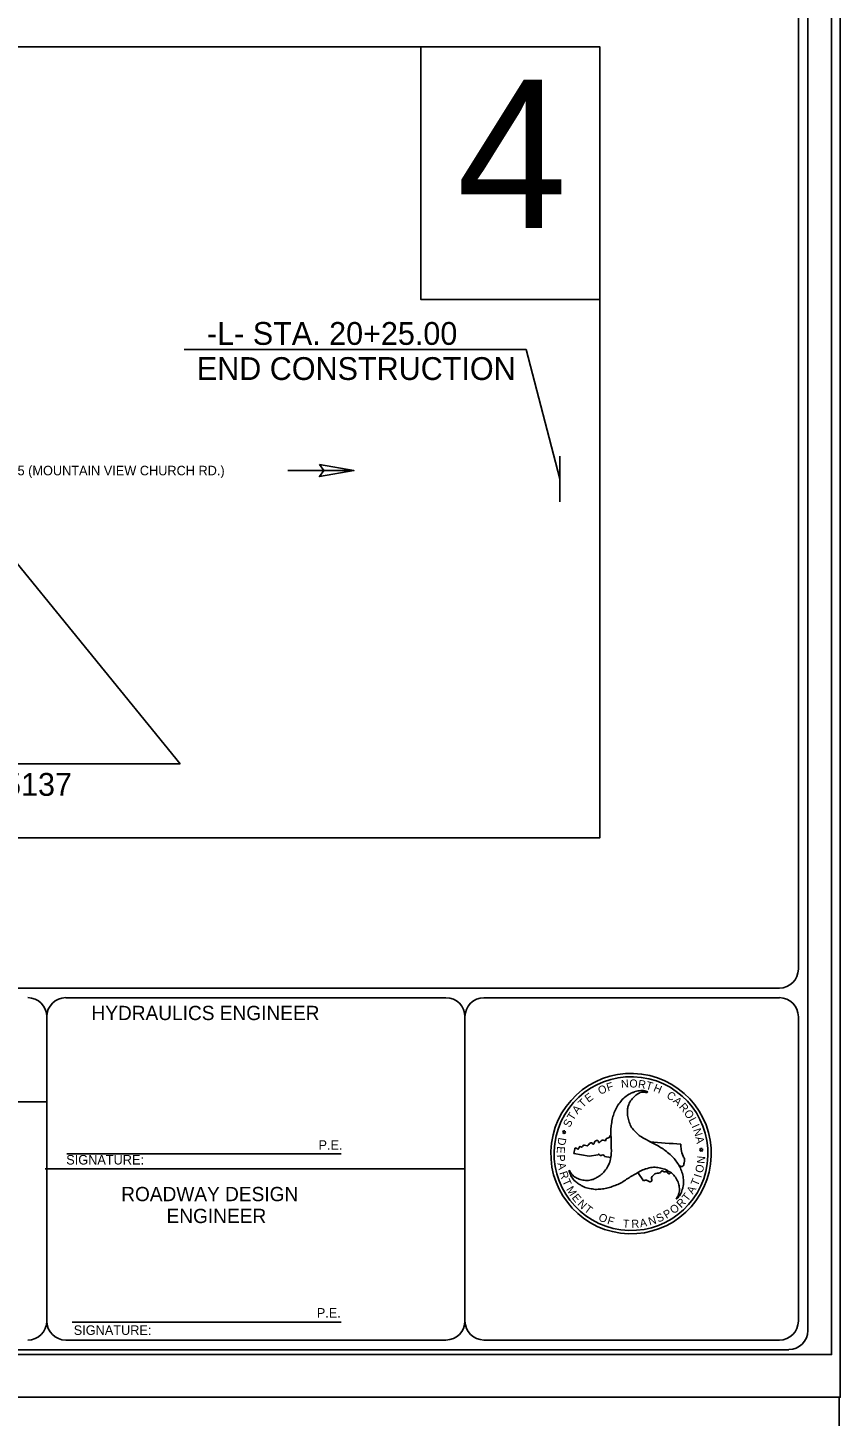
# Model space of a CAD drawing. Extents: x 1664524 to 1666208, y 587901 to 592296.
# Drawn here: x 1665781 to 1666208, y 591186 to 591916 of the extents above; entities that cross this region are included whole.
import ezdxf

# ---------------------------------------------------------------- set-up
doc = ezdxf.new("R2010")
doc.units = 0
for name, color, linetype in [('Default', 7, 'Continuous'), ('Prop Horizontal Alignment Station Label', 7, 'Continuous'), ('Prop Horizontal Alignment Tick Large', 7, 'Continuous'), ('Prop Horizontal Alignment Tick Small', 7, 'Continuous'), ('Prop Terminator CELL', 7, 'Continuous'), ('Sheet Cutting Line CELL', 7, 'Continuous')]:
    doc.layers.add(name, color=color, linetype=linetype)

msp = doc.modelspace()

# ---------------------------------------------------------------- linework, layer by layer
at = {"layer": 'Default'}
for p, q in [((1665863.04, 591747.15), (1666042.63, 591747.15)), ((1666042.63, 591747.15), (1666060.35, 591679.09)), ((1666060.39, 591667.09), (1666060.32, 591691.1)), ((1665860.89, 591529.38), (1665735.9, 591682.77)), ((1665917.52, 591683.48), (1665952.16, 591683.48)), ((1665860.89, 591529.38), (1665603.77, 591529.35))]:
    msp.add_line(p, q, dxfattribs=at)
for points in [[(1665085.75, 591906.14), (1666081.5, 591906.14), (1666081.5, 591490.46), (1665085.75, 591490.46)], [(1666081.5, 591906.14), (1665987.3, 591906.14), (1665987.3, 591773.47), (1666081.5, 591773.47)]]:
    msp.add_lwpolyline(points, close=True, dxfattribs=at)
at = {"layer": 'Prop Horizontal Alignment Station Label'}
for p, q in [((1664755.76, 591411.35), (1666175.76, 591411.35)), ((1665800.76, 591406.35), (1666000.53, 591406.35)), ((1666020.53, 591406.35), (1666175.76, 591406.35)), ((1665790.76, 591236.34), (1665790.76, 591396.34)), ((1666010.53, 591236.35), (1666010.53, 591396.35)), ((1666106.66, 591356.95), (1666106.58, 591356.87)), ((1666106.66, 591356.95), (1666106.58, 591356.87)), ((1665790.76, 591351.59), (1665485.76, 591351.6)), ((1666062.24, 591335.67), (1666061.72, 591336.19)), ((1666061.72, 591336.19), (1666062.45, 591336.09)), ((1666061.94, 591335.01), (1666062.24, 591335.67)), ((1666062.55, 591335.37), (1666061.94, 591335.01)), ((1666062.45, 591336.09), (1666062.74, 591336.73)), ((1666063.09, 591334.86), (1666062.55, 591335.37)), ((1666062.74, 591336.73), (1666062.89, 591336.03)), ((1666062.89, 591336.03), (1666063.61, 591335.93)), ((1666063.61, 591335.93), (1666062.96, 591335.58)), ((1666062.96, 591335.58), (1666063.09, 591334.86)), ((1666107.72, 591330.68), (1666107.72, 591330.68)), ((1666134.81, 591327.38), (1666134.5, 591326.74)), ((1666134.97, 591326.68), (1666134.81, 591327.38)), ((1665801.25, 591324.36), (1665945.5, 591324.36)), ((1666067.84, 591324.41), (1666068.26, 591326.92)), ((1666075.73, 591323.06), (1666067.84, 591324.41)), ((1666080.46, 591323.79), (1666075.73, 591323.06)), ((1666087.19, 591322.33), (1666083.88, 591322.81)), ((1666134.5, 591326.74), (1666133.78, 591326.84)), ((1666133.78, 591326.84), (1666134.32, 591326.34)), ((1666134.32, 591326.34), (1666134.01, 591325.67)), ((1666134.01, 591325.67), (1666134.63, 591326.02)), ((1666134.63, 591326.02), (1666135.15, 591325.52)), ((1666135.68, 591326.61), (1666134.97, 591326.68)), ((1666135.03, 591326.24), (1666135.68, 591326.61)), ((1666135.15, 591325.52), (1666135.03, 591326.24)), ((1665789.86, 591316.37), (1666010.53, 591316.37)), ((1666104.38, 591310.17), (1666101.38, 591314.44)), ((1666101.38, 591314.44), (1666101.38, 591314.44)), ((1666139.63, 591318.87), (1666139.63, 591318.87)), ((1665804.01, 591235.8), (1665945.51, 591235.79))]:
    msp.add_line(p, q, dxfattribs=at)
for points in [[(1666185.76, 591421.34), (1666185.76, 592256.35)], [(1666190.76, 591231.35), (1666190.76, 592261.34)], [(1666185.76, 591236.35), (1666185.76, 591396.35)], [(1665800.76, 591226.35), (1666000.53, 591226.35)], [(1666020.53, 591226.35), (1666175.76, 591226.35)], [(1664700.76, 591221.34), (1666180.76, 591221.34)]]:
    msp.add_lwpolyline(points, dxfattribs=at)
for centre, radius, start, end in [((1666175.76, 591421.39), 10, 270, 360), ((1665780.76, 591396.39), 10, 0, 90), ((1665800.76, 591396.39), 10, 90, 180), ((1666000.53, 591396.35), 10, 0, 90), ((1666020.53, 591396.35), 10, 90, 180), ((1666175.76, 591396.39), 10, 0, 90), ((1666097.83, 591324.42), 42.17, 352.42113, 172.42113), ((1666097.83, 591324.42), 40.42, 352.42113, 172.42113), ((1666097.83, 591324.42), 42.17, 172.42113, 352.42113), ((1666097.83, 591324.42), 40.42, 172.42113, 352.42113), ((1666132.74, 591551.63), 222.36, 258.09962, 258.19922), ((1666132.74, 591551.63), 222.36, 263.53868, 267.74469), ((1665780.76, 591236.39), 10, 270, 360), ((1665800.76, 591236.39), 10, 180, 270), ((1666000.53, 591236.41), 10, 270, 360), ((1666020.53, 591236.41), 10, 180, 270), ((1666175.76, 591236.39), 10, 270, 360), ((1666180.76, 591231.39), 10, 270, 360)]:
    msp.add_arc(centre, radius, start, end, dxfattribs=at)
for points in [[(1666106.58, 591356.87), (1666105.67, 591357.25), (1666102.88, 591357.51), (1666099.93, 591356.98), (1666099.66, 591356.87), (1666098.15, 591356.32), (1666096.51, 591355.4), (1666093.95, 591353.56), (1666091.87, 591351.15), (1666091.02, 591350.12), (1666090.33, 591348.8), (1666089.01, 591345.97), (1666088.15, 591343.19), (1666087.52, 591339.88), (1666087.18, 591336.95), (1666087.26, 591333.9), (1666087.38, 591330.82), (1666087.43, 591327.83), (1666087.44, 591324.77), (1666087.05, 591321.78), (1666087, 591321.52), (1666086.05, 591318.41), (1666084.39, 591315.79), (1666082.42, 591313.67), (1666081.29, 591312.72), (1666079.75, 591311.82), (1666078.87, 591311.29), (1666076.85, 591310.58), (1666073.9, 591310.29), (1666071.12, 591310.82), (1666068.72, 591311.79), (1666066.73, 591313.48), (1666065.27, 591315.71)], [(1666121.6, 591300.54), (1666122.33, 591301.12), (1666123.98, 591303.41), (1666124.99, 591306.23), (1666125.07, 591306.51), (1666125.31, 591308.1), (1666125.34, 591310), (1666125.05, 591313.13), (1666123.98, 591316.12), (1666123.53, 591317.38), (1666122.71, 591318.66), (1666120.93, 591321.21), (1666118.96, 591323.35), (1666116.4, 591325.53), (1666114.02, 591327.27), (1666111.33, 591328.76), (1666108.62, 591330.18), (1666106.04, 591331.62), (1666103.33, 591333.17), (1666100.96, 591334.99), (1666100.78, 591335.18), (1666098.52, 591337.57), (1666097.1, 591340.32), (1666096.23, 591343.07), (1666096.01, 591344.5), (1666096, 591346.3), (1666095.95, 591347.34), (1666096.38, 591349.43), (1666097.6, 591352.15), (1666099.43, 591354.27), (1666101.47, 591355.85), (1666103.95, 591356.73), (1666106.58, 591356.87), (1666106.66, 591356.95)], [(1666068.26, 591326.92), (1666068.21, 591327.16), (1666068.67, 591327.38), (1666069.78, 591326.74), (1666070.44, 591327.17), (1666070.48, 591327.68), (1666071.02, 591328.13), (1666071.81, 591327.86), (1666072.66, 591328.69), (1666073.35, 591328.76), (1666074.76, 591328.57), (1666076.66, 591330.04), (1666077.38, 591330.04), (1666077.5, 591329.57), (1666077.92, 591329.43), (1666078.82, 591330.72), (1666079.03, 591330.89), (1666080.42, 591331.24), (1666080.73, 591330.94), (1666080.75, 591330.31), (1666080.92, 591330.16), (1666081.39, 591330.42), (1666082.07, 591331.08), (1666083.22, 591331.5), (1666084.43, 591331.18), (1666084.78, 591332.16), (1666086.34, 591332.93), (1666086.72, 591333.48), (1666086.87, 591334.06)], [(1666087.26, 591333.97), (1666087.26, 591333.9), (1666087.38, 591330.82), (1666087.43, 591327.83), (1666087.44, 591324.77), (1666087.18, 591322.33)], [(1666123.28, 591317.87), (1666122.71, 591318.66), (1666120.93, 591321.21), (1666118.96, 591323.35), (1666116.4, 591325.53), (1666114.02, 591327.27), (1666111.33, 591328.76), (1666108.62, 591330.18), (1666107.72, 591330.68)], [(1666123.98, 591329.44), (1666124.21, 591326.57), (1666125.23, 591323.09), (1666125.94, 591321.17), (1666125.7, 591319.63), (1666125.1, 591317.83), (1666123.29, 591317.88)], [(1666083.88, 591322.81), (1666083.64, 591323.46), (1666083.02, 591323.73), (1666082.09, 591323.39), (1666081.44, 591323.51), (1666080.79, 591324.13), (1666080.46, 591323.79)], [(1666065.27, 591315.71), (1666065.45, 591314.73), (1666066.61, 591312.18), (1666068.52, 591309.88), (1666068.74, 591309.73), (1666070, 591308.67), (1666071.61, 591307.72), (1666074.49, 591306.4), (1666077.59, 591305.84), (1666078.91, 591305.6), (1666080.47, 591305.67), (1666083.51, 591305.95), (1666086.34, 591306.57), (1666089.54, 591307.69), (1666092.22, 591308.86), (1666094.85, 591310.47), (1666097.44, 591312.13), (1666100.02, 591313.64), (1666102.68, 591315.16), (1666105.45, 591316.34), (1666105.74, 591316.42), (1666108.92, 591317.16), (1666111.98, 591317.03), (1666114.77, 591316.4), (1666116.2, 591315.9), (1666117.71, 591314.98), (1666118.67, 591314.51), (1666120.26, 591313.1), (1666121.97, 591310.69), (1666122.9, 591308.04), (1666123.27, 591305.46), (1666122.8, 591302.89), (1666121.6, 591300.54)], [(1666101.38, 591314.44), (1666102.68, 591315.16), (1666105.45, 591316.34), (1666105.74, 591316.42), (1666108.92, 591317.16), (1666111.98, 591317.03), (1666114.77, 591316.4), (1666116.2, 591315.9), (1666117.71, 591314.98), (1666118.6, 591314.53)], [(1666118.58, 591314.52), (1666118.1, 591313.84), (1666117.46, 591313.88), (1666116.48, 591314.9), (1666115.09, 591314.81), (1666114.52, 591315.25), (1666114.11, 591315.32), (1666112.97, 591314.22), (1666111.59, 591314.1), (1666109.21, 591312.79), (1666108.64, 591311.92), (1666108.53, 591309.89), (1666107.95, 591309.57), (1666107.32, 591309.75), (1666106.05, 591310.45), (1666104.38, 591310.17)]]:
    msp.add_spline(points, degree=3, dxfattribs=at)
at = {"layer": 'Prop Horizontal Alignment Tick Large'}
msp.add_lwpolyline([(1664536.76, 591218.79), (1666203.26, 591218.79), (1666203.26, 592273.89), (1664536.76, 592273.89)], close=True, dxfattribs=at)
at = {"layer": 'Prop Horizontal Alignment Tick Small'}
for points in [[(1666207.76, 592296.34), (1664523.76, 592296.34), (1664523.76, 591196.35), (1666207.76, 591196.35)], [(1664523.76, 590101.35), (1666207.26, 590101.35), (1666207.26, 591196.35), (1664523.76, 591196.35)]]:
    msp.add_lwpolyline(points, close=True, dxfattribs=at)
at = {"layer": 'Prop Terminator CELL'}
msp.add_lwpolyline([(1665934.16, 591686.58), (1665952.16, 591683.48), (1665934.06, 591680.28), (1665936.36, 591683.48)], close=True, dxfattribs=at)
at = {"layer": 'Sheet Cutting Line CELL'}
for p, q in [((1664523.76, 591196.35), (1666207.76, 591196.35)), ((1666207.26, 591196.35), (1664523.76, 591196.35))]:
    msp.add_line(p, q, dxfattribs=at)

# ---------------------------------------------------------------- texts
at = {"layer": 'Default'}
for s, height, p in [('4', 78, (1666006.2, 591810.98)), ('-L- STA. 20+25.00', 12, (1665874.95, 591749.55)), ('END CONSTRUCTION', 12, (1665869.6, 591731.09)), ('TO SR 1545 (MOUNTAIN VIEW CHURCH RD.)', 5, (1665741.95, 591680.98)), ('END TIP PROJECT B-5137', 12, (1665605.13, 591512.49))]:
    msp.add_text(s, height=height, dxfattribs=at).set_placement(p)
at = {"layer": 'Prop Horizontal Alignment Station Label'}
for s, height, rotation, p in [(' HYDRAULICS ENGINEER', 7.5, 360, (1665811.46, 591394.59)), ('E', 4.19, 36.57807, (1666075.4, 591351.1)), ('O', 4.21, 24.63869, (1666081.6, 591355.24)), ('F', 4.21, 17.49185, (1666085.66, 591357.07)), ('N', 4.21, 5.40491, (1666092.75, 591358.89)), ('O', 4.22, 357.9068, (1666096.84, 591359.25)), ('R', 4.21, 351.29687, (1666101.28, 591359.09)), ('T', 4.22, 344.64724, (1666105.26, 591358.49)), ('H', 4.2, 337.56252, (1666109.23, 591357.37)), ('C', 4.19, 325.22017, (1666116.11, 591354.11)), ('A', 4.22, 50.74892, (1666069.66, 591344.9)), ('T', 4.2, 43.6937, (1666072.42, 591348.27)), ('A', 4.2, 317.72314, (1666119.54, 591351.69)), ('R', 4.2, 311.35919, (1666122.74, 591348.8)), ('S', 4.2, 64.17738, (1666065.67, 591337.85)), ('T', 4.21, 57.80123, (1666067.42, 591341.45)), ('O', 4.21, 304.23959, (1666125.39, 591345.77)), ('L', 4.19, 298.00591, (1666127.91, 591342.07)), ('I', 4.21, 294.01657, (1666129.55, 591338.83)), ('N', 4.2, 288.31647, (1666130.35, 591336.94)), ('P.E.', 5, 360, (1665933.55, 591326.4)), ('E', 4.19, 266.56202, (1666058.97, 591328.33)), ('D', 4.21, 260.27413, (1666059.74, 591333.09)), ('A', 4.21, 280.88449, (1666131.62, 591333.01)), ('SIGNATURE:', 5, 360, (1665800.98, 591318.67)), ('P', 4.21, 274.09441, (1666058.78, 591323.76)), ('N', 4.21, 84.62926, (1666136.54, 591318.93)), ('A', 4.2, 280.68699, (1666059.1, 591319.28)), ('R', 4.2, 287.75562, (1666060.08, 591314.4)), ('I', 4.22, 72.24562, (1666134.68, 591311.38)), ('O', 4.19, 77.38125, (1666135.48, 591313.96)), ('ROADWAY DESIGN', 7.4994, 360, (1665829.86, 591299.4)), ('T', 4.2, 294.40616, (1666061.54, 591309.99)), ('M', 4.19, 301.6412, (1666063.57, 591305.67)), ('A', 4.21, 59.51129, (1666130.34, 591302.69)), ('T', 4.2, 66.59571, (1666132.82, 591307.02)), ('E', 4.19, 309.10797, (1666066.45, 591301.17)), ('N', 4.21, 316.07951, (1666069.36, 591297.68)), ('R', 4.21, 45.32446, (1666124.19, 591295.57)), ('T', 4.19, 51.42425, (1666127.43, 591298.92)), ('ENGINEER', 7.499, 360, (1665853.71, 591287.9)), ('T', 4.2, 322.92151, (1666072.81, 591294.42)), ('O', 4.2, 336.2252, (1666080.31, 591289.5)), ('F', 4.2, 343.39043, (1666084.99, 591287.52)), ('N', 4.19, 17.04104, (1666107.64, 591286.61)), ('S', 4.19, 24.25151, (1666112.16, 591288.09)), ('P', 4.2, 31.44336, (1666116.39, 591290.02)), ('O', 4.21, 38.13535, (1666120.22, 591292.4)), ('T', 4.19, 356.29966, (1666093.37, 591285.59)), ('R', 4.21, 3.25628, (1666098.13, 591285.34)), ('A', 4.19, 10.00941, (1666102.76, 591285.67)), ('P.E.', 5, 360, (1665932.66, 591238.2)), ('SIGNATURE:', 5, 360, (1665804.91, 591229.1))]:
    msp.add_text(s, height=height, rotation=rotation, dxfattribs=at).set_placement(p)

doc.saveas('drawing.dxf')
